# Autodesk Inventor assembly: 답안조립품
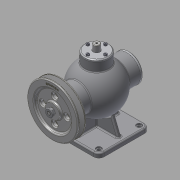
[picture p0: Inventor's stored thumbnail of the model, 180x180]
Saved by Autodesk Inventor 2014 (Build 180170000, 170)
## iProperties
Created: 2015-10
Part Number: 답안조립품
Document SubType Name: Assembly
Designer: youjin13
Author: youjin13
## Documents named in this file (19)
- C:\Users\youjin13\Desktop\451010V1009\답안조립품.iam
- C:\Users\youjin13\Desktop\451010V1009\본체1.ipt
- C:\Users\youjin13\Desktop\451010V1009\뒤커버.ipt
- C:\Users\youjin13\Desktop\451010V1009\앞커버.ipt
- C:\Users\youjin13\Desktop\451010V1009\상부커버.ipt
- C:\Users\youjin13\Desktop\451010V1009\오일실 15 30 7.ipt
- C:\Users\youjin13\Desktop\451010V1009\볼트 M4 x 16.ipt
- C:\Users\youjin13\Desktop\451010V1009\볼트 M 4 x 12.ipt
- C:\Users\youjin13\Desktop\451010V1009\베어링- 6202.ipt
- KS B 2023 - 6202 - 15 x 35 x 11 - 7.8.ipt
- C:\Users\youjin13\Desktop\451010V1009\편심축.ipt
- C:\Users\youjin13\Desktop\451010V1009\부시.ipt
- C:\Users\youjin13\Desktop\451010V1009\키 4 x 4 x 12.ipt
- C:\Users\youjin13\Desktop\451010V1009\멈춤링- 35x1.6.ipt
- KS B 1336 - 35x1.6.ipt
- C:\Users\youjin13\Desktop\451010V1009\멈춤링- 15 x 1.ipt
- C:\Users\youjin13\Desktop\451010V1009\V-벨트풀리.ipt
- C:\Users\youjin13\Desktop\451010V1009\너트 M8.ipt
- C:\Users\youjin13\Desktop\451010V1009\슬라이드.ipt
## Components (16 placed, 5 different names)
1. KS B 2023 - 6202 - 15 x 35 x 11 - 7.8:1 — Mate:14, Mate:15, Mate:31, Mate:32, Mate:33, Angle:1
2. KS B 2023 - 6202 - 15 x 35 x 11 - 7.8:2 — Mate:12, Mate:13, Mate:16, Mate:25, Angle:2
3. KS B 1336 - 35x1.6:1 — Mate:31, Mate:32, Angle:4
4. V-벨트풀리:1 — Mate:35, Flush:1, Mate:36
5. ISO 4762 M4 x 16:1 — Insert:1
6. ISO 4762 M4 x 16:3
7. ISO 4762 M4 x 16:4
8. ISO 4762 M4 x 16:5
9. ISO 4762 M4 x 16:2 — Insert:2
10. ISO 4762 M4 x 16:6
11. ISO 4762 M4 x 16:7
12. ISO 4762 M4 x 16:8
13. KS B 1021 - 에 따름 ISO 1207 - 미터 A  M 4 x 12:1 — Insert:3
14. KS B 1021 - 에 따름 ISO 1207 - 미터 A  M 4 x 12:2
15. KS B 1021 - 에 따름 ISO 1207 - 미터 A  M 4 x 12:3
16. KS B 1021 - 에 따름 ISO 1207 - 미터 A  M 4 x 12:4
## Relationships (18: Mate 11, Insert 3, Angle 3, Flush 1)
- Insert:1: ISO 4762 M4 x 16:1
- Insert:2: ISO 4762 M4 x 16:2
- Insert:3: KS B 1021 - 에 따름 ISO 1207 - 미터 A  M 4 x 12:1
- Mate:12: KS B 2023 - 6202 - 15 x 35 x 11 - 7.8:2
- Mate:13: KS B 2023 - 6202 - 15 x 35 x 11 - 7.8:2
- Mate:14: KS B 2023 - 6202 - 15 x 35 x 11 - 7.8:1
- Mate:15: KS B 2023 - 6202 - 15 x 35 x 11 - 7.8:1
- Mate:16: KS B 2023 - 6202 - 15 x 35 x 11 - 7.8:2
- Mate:25: KS B 2023 - 6202 - 15 x 35 x 11 - 7.8:2
- Mate:31: KS B 2023 - 6202 - 15 x 35 x 11 - 7.8:1 ↔ KS B 1336 - 35x1.6:1
- Mate:32: KS B 2023 - 6202 - 15 x 35 x 11 - 7.8:1 ↔ KS B 1336 - 35x1.6:1
- Mate:33: KS B 2023 - 6202 - 15 x 35 x 11 - 7.8:1
- Mate:35: V-벨트풀리:1
- Flush:1: V-벨트풀리:1
- Mate:36: V-벨트풀리:1
- Angle:1: KS B 2023 - 6202 - 15 x 35 x 11 - 7.8:1
- Angle:2: KS B 2023 - 6202 - 15 x 35 x 11 - 7.8:2
- Angle:4: KS B 1336 - 35x1.6:1
